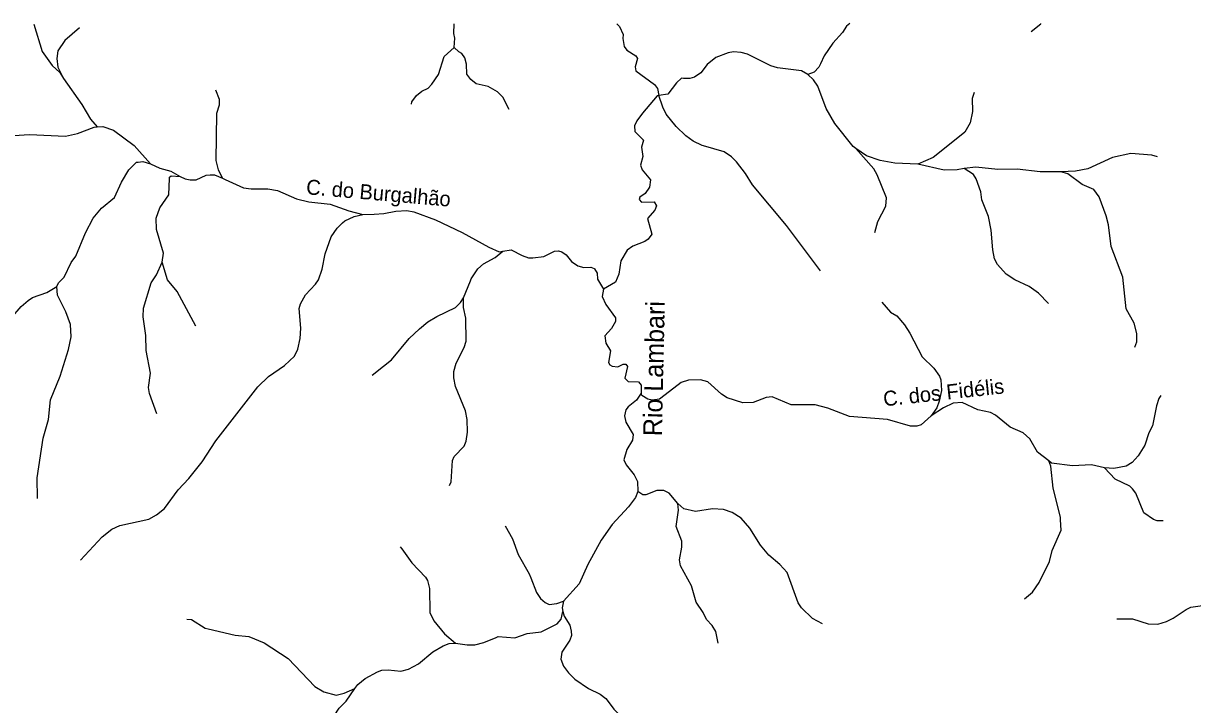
# Model space of a CAD drawing. Extents: x 473.9 to 500, y 7733.1 to 7760.8.
# Drawn here: x 481.48 to 487.72, y 7757.18 to 7760.82 of the extents above; entities that cross this region are included whole.
import ezdxf
from ezdxf.enums import TextEntityAlignment as Align

# ---------------------------------------------------------------- set-up
doc = ezdxf.new("R2010")
doc.units = 0
doc.header["$LTSCALE"] = 0.032
doc.layers.add('61', color=7, linetype='Continuous')
doc.layers.add('7', color=7, linetype='Continuous', lineweight=25)

msp = doc.modelspace()

# ---------------------------------------------------------------- linework, layer by layer
at = {"layer": '7'}
for points in [[(481.5392, 7760.8111), (481.5837, 7760.666), (481.6362, 7760.5901), (481.6785, 7760.5535), (481.6971, 7760.5208)], [(483.782, 7760.6872), (483.7863, 7760.7363), (483.78, 7760.7613), (483.7823, 7760.8128)], [(484.6506, 7760.8134), (484.6514, 7760.8126), (484.6642, 7760.7991), (484.6849, 7760.7555), (484.6828, 7760.734), (484.6902, 7760.6912), (484.7037, 7760.6719), (484.7515, 7760.6423), (484.7609, 7760.6276), (484.7478, 7760.5841), (484.7523, 7760.5617), (484.8517, 7760.49), (484.8671, 7760.468), (484.8754, 7760.4302)], [(485.8948, 7760.8144), (485.877, 7760.8004), (485.8543, 7760.766), (485.8038, 7760.7097), (485.757, 7760.6419), (485.737, 7760.5989), (485.7287, 7760.5812), (485.7042, 7760.5556), (485.6699, 7760.5424)], [(486.8616, 7760.7715), (486.9131, 7760.8135), (486.914, 7760.8151)], [(481.7834, 7760.7911), (481.7043, 7760.7232), (481.6665, 7760.668), (481.6616, 7760.6277), (481.6669, 7760.5822), (481.6971, 7760.5208)], [(483.5542, 7760.3835), (483.5557, 7760.3964), (483.5808, 7760.4301), (483.6093, 7760.4529), (483.6441, 7760.4704), (483.6639, 7760.4901), (483.6987, 7760.543), (483.7284, 7760.6384), (483.782, 7760.6872)], [(484.0758, 7760.3553), (484.0413, 7760.4216), (484.0133, 7760.4497), (483.9642, 7760.4786), (483.8994, 7760.4934), (483.8707, 7760.5152), (483.8506, 7760.5439), (483.8489, 7760.5984), (483.84, 7760.632), (483.824, 7760.6548), (483.807, 7760.6631), (483.782, 7760.6872)], [(485.6699, 7760.5424), (485.6358, 7760.5627), (485.5072, 7760.5784), (485.4724, 7760.5882), (485.3476, 7760.6504), (485.3143, 7760.6606), (485.2725, 7760.6637), (485.2444, 7760.6586), (485.1786, 7760.6333), (485.1331, 7760.5954), (485.0997, 7760.5516), (485.0654, 7760.5279), (485.0407, 7760.5203), (485.0057, 7760.5219), (484.9961, 7760.5224), (484.9696, 7760.4976), (484.9233, 7760.4377), (484.8754, 7760.4302)], [(481.6971, 7760.5208), (481.7955, 7760.3831), (481.8405, 7760.304), (481.8772, 7760.2632)], [(485.9254, 7760.1484), (485.9119, 7760.158), (485.8147, 7760.2808), (485.7677, 7760.3604), (485.7226, 7760.4796), (485.7008, 7760.5149), (485.6699, 7760.5424)], [(482.5078, 7760.4608), (482.5286, 7760.4107), (482.5279, 7760.3792), (482.514, 7760.3343), (482.5108, 7760.0829), (482.5225, 7760.0343), (482.5451, 7759.9893)], [(486.5581, 7760.4459), (486.5468, 7760.4144), (486.5482, 7760.3456), (486.5366, 7760.284), (486.5074, 7760.2346), (486.4433, 7760.1837), (486.3382, 7760.1004), (486.2571, 7760.0634)], [(484.8754, 7760.4302), (484.8653, 7760.4292), (484.787, 7760.3366), (484.7572, 7760.2962), (484.7453, 7760.2682), (484.7469, 7760.2392), (484.7925, 7760.192), (484.7823, 7760.155), (484.7902, 7760.1042), (484.7766, 7760.0596), (484.7857, 7760.0333), (484.8294, 7759.9806), (484.8253, 7759.9419), (484.8013, 7759.908), (484.7739, 7759.8881), (484.7704, 7759.876), (484.7825, 7759.8619), (484.8495, 7759.8626), (484.8629, 7759.8415), (484.8534, 7759.8187), (484.8143, 7759.7745), (484.8367, 7759.6915), (484.8182, 7759.6648), (484.8, 7759.6521), (484.736, 7759.6272), (484.7059, 7759.606), (484.6717, 7759.5481), (484.6611, 7759.4772), (484.6433, 7759.434), (484.5796, 7759.3974)], [(485.7367, 7759.4957), (485.5567, 7759.7369), (485.3744, 7759.9544), (485.3374, 7760.0149), (485.2887, 7760.0771), (485.2619, 7760.1039), (485.2235, 7760.1296), (485.1125, 7760.1615), (485.1054, 7760.1635), (485.0578, 7760.1864), (485.0186, 7760.2155), (484.9669, 7760.2659), (484.9147, 7760.33), (484.8956, 7760.3677), (484.8754, 7760.4302)], [(481.0832, 7760.1361), (481.1147, 7760.1475), (481.2679, 7760.1781), (481.3772, 7760.213), (481.5149, 7760.2221), (481.7071, 7760.2132), (481.7717, 7760.228), (481.8606, 7760.262), (481.8772, 7760.2632)], [(481.8772, 7760.2632), (481.9074, 7760.2654), (481.9641, 7760.2464), (482.0748, 7760.1632), (482.1609, 7760.0651)], [(486.2571, 7760.0634), (486.1337, 7760.0689), (486.0567, 7760.0833), (485.9822, 7760.108), (485.9254, 7760.1484)], [(486.028, 7759.6999), (486.0442, 7759.7577), (486.0861, 7759.8401), (486.089, 7759.885), (486.0407, 7760.0081), (486.0214, 7760.0392), (485.9254, 7760.1484)], [(481.6622, 7759.411), (481.6704, 7759.4316), (481.7005, 7759.4613), (481.7388, 7759.5399), (481.7635, 7759.5734), (481.8142, 7759.6971), (481.8551, 7759.7757), (481.9004, 7759.8298), (481.9697, 7759.8871), (482.0063, 7759.9675), (482.0455, 7760.0341), (482.0874, 7760.0744), (482.0949, 7760.0752), (482.1214, 7760.0781), (482.1609, 7760.0651)], [(482.1609, 7760.0651), (482.2107, 7760.042), (482.2701, 7760.0277), (482.3207, 7759.9989)], [(486.5044, 7760.0412), (486.4672, 7760.0343), (486.3977, 7760.033), (486.2571, 7760.0634)], [(487.5357, 7760.1024), (487.5051, 7760.1121), (487.3931, 7760.121), (487.2969, 7760.1002), (487.1637, 7760.0398), (487.0984, 7760.0272), (487.0195, 7760.0237)], [(482.2247, 7759.5408), (482.2303, 7759.5887), (482.1942, 7759.7154), (482.1925, 7759.7754), (482.2111, 7759.8304), (482.2592, 7759.9011), (482.2632, 7759.9881), (482.2635, 7759.9947), (482.2724, 7760.0018), (482.3207, 7759.9989)], [(482.3207, 7759.9989), (482.3458, 7759.986), (482.373, 7759.9807), (482.405, 7759.9807), (482.4593, 7760.0049), (482.4804, 7760.0079), (482.5032, 7760.0064), (482.5451, 7759.9893)], [(487.0195, 7760.0237), (486.9102, 7760.0234), (486.7879, 7760.0383), (486.6849, 7760.0352), (486.567, 7760.0481), (486.5044, 7760.0412)], [(486.9549, 7759.3201), (486.9018, 7759.3765), (486.8511, 7759.4121), (486.7746, 7759.4464), (486.7284, 7759.4776), (486.6821, 7759.5296), (486.6666, 7759.5588), (486.6568, 7759.6067), (486.6487, 7759.7128), (486.6342, 7759.7853), (486.5989, 7759.8738), (486.5942, 7759.917), (486.5692, 7759.9857), (486.5549, 7760.0087), (486.5044, 7760.0412)], [(487.4157, 7759.0883), (487.4259, 7759.1166), (487.4259, 7759.1606), (487.4115, 7759.2166), (487.3693, 7759.2921), (487.3512, 7759.4608), (487.2886, 7759.6243), (487.2741, 7759.7404), (487.2619, 7759.7889), (487.224, 7759.8902), (487.196, 7759.9296), (487.1342, 7759.9563), (487.0579, 7760.0118), (487.0195, 7760.0237)], [(482.5451, 7759.9893), (482.5597, 7759.9826), (482.6576, 7759.9377), (482.6996, 7759.9318), (482.7877, 7759.9325), (482.8387, 7759.9245), (482.941, 7759.8798), (483.0058, 7759.8636), (483.1213, 7759.8515), (483.2206, 7759.8145), (483.2941, 7759.7957)], [(483.2941, 7759.7957), (483.355, 7759.797), (483.4062, 7759.8004), (483.4715, 7759.8129), (483.5298, 7759.8171), (483.567, 7759.8094), (483.6834, 7759.7675), (483.8245, 7759.6994), (483.9672, 7759.6208), (484.0219, 7759.5969), (484.0417, 7759.5999)], [(481.7881, 7757.9515), (481.9041, 7758.0759), (481.9558, 7758.1167), (481.9971, 7758.1358), (482.1527, 7758.1708), (482.1938, 7758.1927), (482.236, 7758.2274), (482.3084, 7758.3262), (482.3662, 7758.3873), (482.4372, 7758.476), (482.5108, 7758.5887), (482.7349, 7758.8763), (482.7919, 7758.9317), (482.876, 7758.991), (482.9295, 7759.0396), (482.948, 7759.0769), (482.9605, 7759.1336), (482.9638, 7759.1896), (482.9557, 7759.2938), (482.9619, 7759.3194), (482.9892, 7759.3679), (483.0429, 7759.4232), (483.0582, 7759.4479), (483.0777, 7759.5047), (483.094, 7759.5862), (483.1253, 7759.6764), (483.157, 7759.7225), (483.1868, 7759.7505), (483.1982, 7759.7611), (483.2493, 7759.7854), (483.2941, 7759.7957)], [(483.8327, 7759.352), (483.8687, 7759.4426), (483.8726, 7759.4525), (483.9095, 7759.5054), (483.9393, 7759.532), (484.0015, 7759.5657), (484.0417, 7759.5999)], [(484.0417, 7759.5999), (484.0869, 7759.6069), (484.1449, 7759.5777), (484.1796, 7759.5653), (484.2029, 7759.5646), (484.2603, 7759.5723), (484.3176, 7759.6002), (484.3395, 7759.6021), (484.3578, 7759.5962), (484.38, 7759.5803), (484.4088, 7759.5441), (484.4421, 7759.5212), (484.4736, 7759.5125), (484.5112, 7759.514), (484.5292, 7759.5071), (484.5306, 7759.5066), (484.5448, 7759.4833), (484.5465, 7759.4502), (484.5796, 7759.3974)], [(482.1958, 7758.7328), (482.1571, 7758.8408), (482.1509, 7758.8732), (482.1611, 7758.9501), (482.138, 7759.0707), (482.1363, 7759.15), (482.122, 7759.2503), (482.1236, 7759.2959), (482.1649, 7759.4317), (482.1928, 7759.4746), (482.2247, 7759.5408)], [(482.4033, 7759.2002), (482.3035, 7759.3851), (482.2518, 7759.4467), (482.2247, 7759.5408)], [(481.1236, 7759.079), (481.1546, 7759.0805), (481.2361, 7759.105), (481.3094, 7759.1402), (481.3612, 7759.1766), (481.4711, 7759.3049), (481.5079, 7759.3362), (481.5325, 7759.3527), (481.6077, 7759.3804), (481.6622, 7759.411)], [(481.5584, 7758.2799), (481.5559, 7758.3902), (481.5888, 7758.6019), (481.6175, 7758.7023), (481.6281, 7758.8071), (481.6794, 7758.9338), (481.7236, 7759.0753), (481.7379, 7759.1427), (481.7347, 7759.209), (481.7099, 7759.2764), (481.6644, 7759.3654), (481.6622, 7759.411)], [(484.5796, 7759.3974), (484.5727, 7759.3587), (484.5925, 7759.3159), (484.6428, 7759.2448), (484.6443, 7759.2248), (484.6213, 7759.1874), (484.5866, 7759.148), (484.591, 7759.1094), (484.617, 7759.0679), (484.6064, 7759.0067), (484.6135, 7758.9929), (484.6262, 7758.9864), (484.6554, 7758.9836), (484.6841, 7758.9974), (484.6984, 7758.998), (484.7083, 7758.984), (484.6931, 7758.9229), (484.7104, 7758.9055), (484.7661, 7758.9037), (484.7805, 7758.8846), (484.7801, 7758.8426)], [(483.3452, 7758.939), (483.4044, 7758.9862), (483.4478, 7759.0207), (483.5416, 7759.1345), (483.5966, 7759.1857), (483.6423, 7759.2231), (483.6891, 7759.2514), (483.7899, 7759.3001), (483.8168, 7759.3262), (483.8327, 7759.352)], [(483.7574, 7758.3494), (483.7667, 7758.3695), (483.7734, 7758.484), (483.7827, 7758.5041), (483.8349, 7758.5591), (483.8467, 7758.5863), (483.8537, 7758.6352), (483.8521, 7758.7029), (483.8427, 7758.7486), (483.7895, 7758.8777), (483.78, 7758.9249), (483.7804, 7758.9576), (483.7922, 7759.0028), (483.8352, 7759.0855), (483.8458, 7759.1202), (483.8441, 7759.243), (483.832, 7759.3003), (483.8327, 7759.352)], [(486.065, 7759.3276), (486.1111, 7759.2744), (486.1458, 7759.2545), (486.1863, 7759.2075), (486.2148, 7759.1631), (486.2795, 7759.0356), (486.3422, 7758.9755), (486.3728, 7758.9338), (486.3794, 7758.914), (486.3834, 7758.8576), (486.3717, 7758.7999), (486.3576, 7758.7649), (486.329, 7758.7214)], [(486.329, 7758.7214), (486.2757, 7758.6734), (486.2526, 7758.6658), (486.2183, 7758.6658), (486.0959, 7758.7026), (485.8922, 7758.7173), (485.7759, 7758.7618), (485.7094, 7758.7795), (485.5804, 7758.7804), (485.4788, 7758.8235), (485.4472, 7758.82), (485.3776, 7758.7922), (485.3223, 7758.7909), (485.2398, 7758.8178), (485.2092, 7758.8365), (485.1364, 7758.9034), (485.0972, 7758.9142), (485.0335, 7758.9112), (484.9939, 7758.899), (484.9553, 7758.8699), (484.8775, 7758.8112), (484.8388, 7758.8053), (484.8164, 7758.8105), (484.7836, 7758.8297), (484.7801, 7758.8426)], [(484.7801, 7758.8426), (484.7552, 7758.8049), (484.7114, 7758.7704), (484.6987, 7758.7535), (484.6917, 7758.7222), (484.6987, 7758.687), (484.7373, 7758.622), (484.7333, 7758.5918), (484.7035, 7758.5419), (484.6886, 7758.4878), (484.7001, 7758.4597), (484.7435, 7758.4062), (484.7612, 7758.3716), (484.7626, 7758.3178)], [(487.5532, 7758.8299), (487.5427, 7758.8147), (487.5317, 7758.7754), (487.5104, 7758.6683), (487.4904, 7758.6306), (487.4688, 7758.5645), (487.4333, 7758.508), (487.4013, 7758.473), (487.3698, 7758.4528), (487.3025, 7758.4405), (487.2536, 7758.4445)], [(486.9555, 7758.4815), (486.8963, 7758.528), (486.8554, 7758.5987), (486.8194, 7758.6308), (486.7498, 7758.6603), (486.6715, 7758.7256), (486.6456, 7758.7397), (486.578, 7758.7538), (486.4945, 7758.7932), (486.4458, 7758.7886), (486.3941, 7758.7645), (486.329, 7758.7214)], [(486.8268, 7757.7449), (486.8683, 7757.7808), (486.9053, 7757.833), (486.9601, 7757.9447), (486.9749, 7758.0037), (487.0223, 7758.1126), (487.019, 7758.167), (487.0182, 7758.1805), (486.9792, 7758.3361), (486.967, 7758.4524), (486.9555, 7758.4815)], [(487.2536, 7758.4445), (487.184, 7758.4597), (487.083, 7758.4549), (486.9707, 7758.4695), (486.9555, 7758.4815)], [(487.5662, 7758.1617), (487.5348, 7758.1615), (487.5144, 7758.1688), (487.4624, 7758.205), (487.4205, 7758.3087), (487.402, 7758.3327), (487.388, 7758.3458), (487.3103, 7758.3837), (487.2536, 7758.4445)], [(484.7626, 7758.3178), (484.7508, 7758.2864), (484.7126, 7758.2354), (484.6258, 7758.1421), (484.5663, 7758.0584), (484.4953, 7757.9285), (484.4498, 7757.8247), (484.3662, 7757.7324)], [(484.9758, 7758.2534), (484.93, 7758.3087), (484.9021, 7758.3226), (484.864, 7758.3241), (484.8062, 7758.301), (484.7885, 7758.3011), (484.7626, 7758.3178)], [(485.1916, 7757.5082), (485.179, 7757.5708), (485.1597, 7757.6027), (485.1294, 7757.6347), (485.1122, 7757.6719), (485.0741, 7757.7271), (485.0495, 7757.8152), (484.9895, 7757.9222), (484.9843, 7757.9533), (484.9971, 7758.0202), (484.9971, 7758.0524), (484.9667, 7758.1314), (484.9802, 7758.2177), (484.9758, 7758.2534)], [(485.7489, 7757.6127), (485.694, 7757.6399), (485.6367, 7757.6975), (485.6176, 7757.7248), (485.5589, 7757.8851), (485.5212, 7757.9284), (485.4616, 7757.9792), (485.4176, 7758.0314), (485.3607, 7758.1231), (485.3141, 7758.1751), (485.2659, 7758.2051), (485.2207, 7758.2214), (485.1619, 7758.2247), (485.07, 7758.212), (485.0089, 7758.2263), (484.9758, 7758.2534)], [(484.0542, 7758.1348), (484.0934, 7758.066), (484.1235, 7757.9818), (484.1831, 7757.8787), (484.1911, 7757.858), (484.222, 7757.7784), (484.2433, 7757.7475), (484.268, 7757.7256), (484.29, 7757.7149), (484.3306, 7757.7198), (484.3662, 7757.7324)], [(483.4945, 7758.0231), (483.5022, 7758.0126), (483.5569, 7757.938), (483.6292, 7757.8607), (483.6392, 7757.8425), (483.6501, 7757.8014), (483.6518, 7757.6719), (483.6733, 7757.6283), (483.7312, 7757.559), (483.7895, 7757.5086)], [(484.3662, 7757.7324), (484.3595, 7757.6979), (484.3617, 7757.6785)], [(487.3193, 7757.6394), (487.4027, 7757.6386), (487.4861, 7757.6114), (487.5378, 7757.6107), (487.5838, 7757.6239), (487.62, 7757.642), (487.6884, 7757.689), (487.7143, 7757.7004), (487.7772, 7757.7093), (487.8428, 7757.7021), (487.9615, 7757.7069), (487.9849, 7757.7034), (487.9986, 7757.7013), (488.0871, 7757.67), (488.1564, 7757.6295)], [(482.355, 7757.6361), (482.3809, 7757.6351), (482.4538, 7757.5898), (482.4691, 7757.5861), (482.6129, 7757.5515), (482.6863, 7757.5448), (482.7689, 7757.5108), (482.897, 7757.4263), (483.0392, 7757.2771), (483.0859, 7757.2487), (483.1517, 7757.2322), (483.1958, 7757.2416), (483.2529, 7757.2663)], [(483.7895, 7757.5086), (483.8518, 7757.4992), (483.8925, 7757.5009), (483.9412, 7757.5133), (484.0058, 7757.54), (484.0173, 7757.5447), (484.1059, 7757.5369), (484.1719, 7757.5601), (484.2473, 7757.57), (484.3322, 7757.6113), (484.3533, 7757.6374), (484.3617, 7757.6785)], [(484.3617, 7757.6785), (484.3696, 7757.6537), (484.3997, 7757.6046), (484.4076, 7757.5725), (484.4085, 7757.5496), (484.3995, 7757.5253), (484.3562, 7757.4607), (484.3525, 7757.4238), (484.3665, 7757.3869), (484.3918, 7757.3498), (484.4257, 7757.3168), (484.4991, 7757.267), (484.5622, 7757.2371), (484.5917, 7757.2129), (484.6147, 7757.1838), (484.6338, 7757.1564), (484.6615, 7757.1301), (484.6887, 7757.1117)], [(483.2529, 7757.2663), (483.2688, 7757.2885), (483.3075, 7757.3199), (483.3739, 7757.3563), (483.3967, 7757.3644), (483.4308, 7757.3668), (483.4977, 7757.3589), (483.5391, 7757.3699), (483.5918, 7757.3993), (483.6678, 7757.463), (483.7228, 7757.495), (483.7563, 7757.5068), (483.7895, 7757.5086)], [(482.1549, 7757.0494), (482.1985, 7756.996), (482.2187, 7756.9591), (482.2656, 7756.8963), (482.3553, 7756.8147), (482.389, 7756.8041), (482.4519, 7756.7976), (482.5337, 7756.764), (482.6514, 7756.7505), (482.7024, 7756.7446), (482.7852, 7756.7008), (482.8516, 7756.6878), (482.9087, 7756.7087), (482.9433, 7756.7465), (482.9877, 7756.8632), (483.0778, 7756.9951), (483.1148, 7757.0805), (483.1682, 7757.1627), (483.2053, 7757.1995), (483.2529, 7757.2663)]]:
    msp.add_lwpolyline(points, dxfattribs=at)

# ---------------------------------------------------------------- texts
at = {"layer": '61'}
for s, height, rotation, p in [('C. do Burgalhão', 0.08, 355.075, (483.3751, 7759.8707)), ('Rio Lambari', 0.1, 88.744, (484.8988, 7758.9724)), ('C. dos Fidélis', 0.08, 6.17, (486.3988, 7758.8067))]:
    msp.add_text(s, height=height, rotation=rotation, dxfattribs=at).set_placement(p, align=Align.CENTER)

doc.saveas('drawing.dxf')
